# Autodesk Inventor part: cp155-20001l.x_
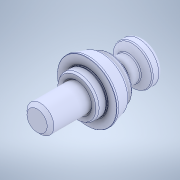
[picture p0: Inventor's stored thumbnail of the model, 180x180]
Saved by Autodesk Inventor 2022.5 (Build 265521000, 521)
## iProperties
Created: 2023-05
Part Number: cp155-20001l.x_
Material: Generic
Document SubType Name: Modeling
Designer: ImaoCorp
Density: 1 g/cm^3
Appearance: Default
Sending System: SOLIDWORKS 2021-2021301
MC: AMD64
MC_MODEL: Intel64 Family 6 Model 60 Stepping 3, GenuineIntel
OS: Windows_NT
FRU: Parasolid Version 32.1, build 255,  1- 1-2021
FORMAT: text
GUISE: transmit
KEY: cp155-20001l
FILE: cp155-20001l.x_t
DATE: Fri May 26 11:42:20 2023
Author: ImaoCorp
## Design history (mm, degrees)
feature "Base1"
node "ソリッド1"
